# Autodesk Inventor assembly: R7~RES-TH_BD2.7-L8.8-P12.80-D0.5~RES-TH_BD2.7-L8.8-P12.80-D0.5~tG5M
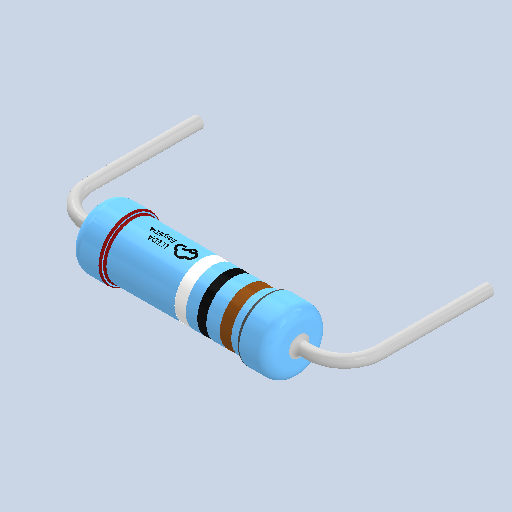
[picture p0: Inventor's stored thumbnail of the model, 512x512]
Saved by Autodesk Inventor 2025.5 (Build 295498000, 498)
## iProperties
Created: 2026-10
Part Number: R7~RES-TH_BD2.7-L8.8-P12.80-D0.5~RES-TH_BD2.7-L8.8-P12.80-D0.5~tG5M
Document SubType Name: Assembly
Designer: Luis M
Author: Luis M
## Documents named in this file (2)
- C:\Users\Luis M\Downloads\3D_PCB1_2026-10-28\R7~RES-TH_BD2.7-L8.8-P12.80-D0.5~RES-TH_BD2.7-L8.8-P12.80-D0.5~tG5M.iam
- C:\Users\Luis M\Downloads\3D_PCB1_2026-10-28\RES-TH_BD2.7-L8.8-P12.80-D0.5~RES-TH_BD2.7-L8.8-P12.80-D0.5~UAzC.ipt
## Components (1 placed, 1 different names)
1. R7->0
